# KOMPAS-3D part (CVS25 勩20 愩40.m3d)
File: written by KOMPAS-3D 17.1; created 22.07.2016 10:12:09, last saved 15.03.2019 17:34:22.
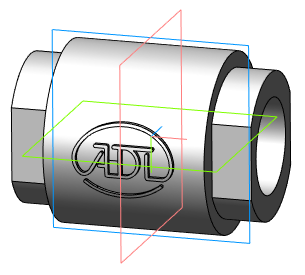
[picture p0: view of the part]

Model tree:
1. Операция без истории:2  (labels: Сталь 20  ГОСТ 1050-88)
